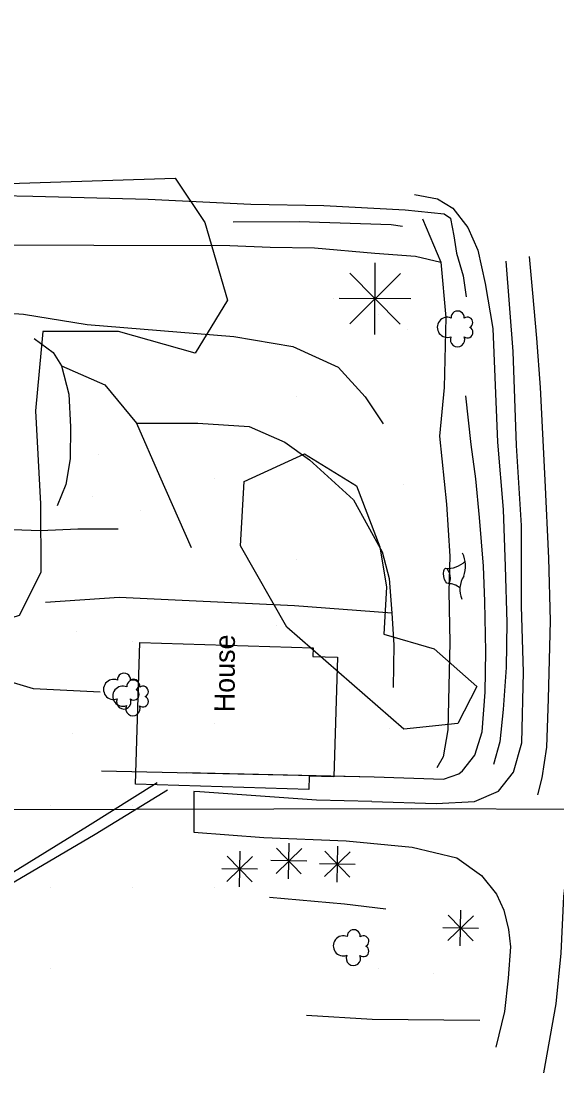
# Model space of a CAD drawing. Extents: x 19528164 to 19545171, y 7585743 to 7602745.
# Drawn here: x 19529637.7 to 19529768.7, y 7587529.5 to 7587786.8 of the extents above; entities that cross this region are included whole.
import ezdxf

# ---------------------------------------------------------------- set-up
doc = ezdxf.new("R2010")
doc.units = 0
for name, color, linetype in [('Default', 7, 'Continuous'), ('PhoBreakLine', 7, 'Continuous'), ('PhoBuilding', 7, 'Continuous'), ('PhoEdgeSidewalk', 7, 'Continuous'), ('PhoISAEPoints', 7, 'Continuous'), ('PhoNotesDesign', 7, 'Continuous'), ('PhoSurveyLimits', 7, 'Continuous'), ('PhoVegetation', 7, 'Continuous'), ('SurBreakLine', 7, 'Continuous'), ('SurEdgeEntranceUnpaved', 7, 'Continuous'), ('SurROWRail', 7, 'Continuous')]:
    doc.layers.add(name, color=color, linetype=linetype)

# ---------------------------------------------------------------- blocks, each defined once
blk = doc.blocks.new('TREV')
at = {"layer": 'Default'}
for p, q in [((0, -8.75), (0, 8.75)), ((-6.18, -6.19), (6.19, 6.18)), ((6.18, -6.18), (-6.18, 6.18)), ((-8.75, 0), (8.75, 0)), ((0, 0), (0, 0))]:
    blk.add_line(p, q, dxfattribs=at)
blk = doc.blocks.new('TRDC')
at = {"layer": 'PhoVegetation'}
for centre, radius, start, end in [((0.07, 3.96), 4.92, 338.2051, 201.7949), ((-5.96, -1.07), 3.52, 65.4824, 294.5175), ((4.86, -1.07), 3.21, 265.9982, 94.0018), ((-2.37, -5.89), 2.68, 142.7501, 335.3223), ((2.46, -5.82), 2.67, 206.5242, 35.4033)]:
    blk.add_arc(centre, radius, start, end, dxfattribs=at)

msp = doc.modelspace()

# ---------------------------------------------------------------- linework, layer by layer
at = {"layer": 'PhoBreakLine'}
for points in [[(19529420.19, 7587746.61), (19529433.66, 7587746.58), (19529450.79, 7587746.1), (19529465.72, 7587745.84), (19529493.29, 7587745.02), (19529503.44, 7587744.9), (19529528.05, 7587744.66), (19529553.91, 7587744.62), (19529574.34, 7587744.69), (19529588.8, 7587744.24), (19529624.68, 7587744.31), (19529640.57, 7587743.93), (19529668.81, 7587743.19), (19529693.9, 7587741.96), (19529711.72, 7587741.66)], [(19529733.91, 7587744.35), (19529739.52, 7587743.26), (19529743.28, 7587741.05), (19529746.97, 7587736.28), (19529749.38, 7587730.72), (19529751.16, 7587722.61), (19529753.05, 7587711.57), (19529754.21, 7587683.76), (19529755.58, 7587667.29), (19529756.09, 7587653.39), (19529756.43, 7587639.73), (19529756.31, 7587628.69), (19529755.56, 7587618.43), (19529754.77, 7587610.51), (19529753.2, 7587604.95)], [(19529156.27, 7587739.82), (19529168.3, 7587739.53), (19529192.58, 7587740.59), (19529208.56, 7587740.78), (19529236.73, 7587740.12), (19529269.19, 7587739.6), (19529293.66, 7587738.67), (19529340.18, 7587738.62), (19529352.73, 7587738.2), (19529419.89, 7587736.21), (19529440.4, 7587735.64), (19529452.89, 7587735.05), (19529493.33, 7587731.91), (19529550.24, 7587733.18), (19529571.65, 7587732.68), (19529583.99, 7587732.56), (19529601.39, 7587732.73), (19529622.17, 7587732.03), (19529688.78, 7587731.89)], [(19529711.72, 7587741.66), (19529731.6, 7587740.61), (19529741.13, 7587739.6), (19529742.67, 7587738.55), (19529742.67, 7587738.53), (19529743.49, 7587734.23), (19529744.17, 7587730.03), (19529745.8, 7587724.47), (19529746.52, 7587719.34)], [(19529689.61, 7587737.66), (19529705.72, 7587737.72), (19529728.21, 7587736.99), (19529730.99, 7587736.58)], [(19529735.82, 7587738.38), (19529740.34, 7587727.82), (19529741.58, 7587714.3), (19529741.12, 7587697.15), (19529739.97, 7587685.24), (19529741.73, 7587668.61), (19529742.5, 7587655.88), (19529742.29, 7587647.28), (19529742.53, 7587634.79)], [(19529688.78, 7587731.89), (19529698.6, 7587731.44), (19529709.44, 7587731.29), (19529724.21, 7587730.01), (19529734.15, 7587729.31), (19529740.34, 7587727.82)], [(19529761.95, 7587729.17), (19529762.73, 7587720.21), (19529763.72, 7587709.19), (19529764.64, 7587697.14), (19529765.75, 7587674.53), (19529766.68, 7587655.45), (19529767.03, 7587640.08), (19529766.6, 7587621), (19529766.17, 7587609.21), (19529765.05, 7587601.68), (19529763.95, 7587597.53)], [(19529616.13, 7587716.64), (19529638.34, 7587715.08), (19529653.91, 7587712.56), (19529689.77, 7587709.6), (19529704.19, 7587707.22), (19529715.24, 7587702.13), (19529721.86, 7587694.89), (19529726.26, 7587688.26)], [(19529640.96, 7587709.15), (19529645.59, 7587705.73), (19529647.58, 7587702.43), (19529649.39, 7587695.49), (19529649.79, 7587687.53), (19529649.7, 7587679.74), (19529648.66, 7587673.47), (19529646.51, 7587668.24)], [(19529647.58, 7587702.43), (19529658.21, 7587697.82), (19529665.92, 7587688.41), (19529671.59, 7587675.53), (19529679.3, 7587658.01)], [(19529745.65, 7587603.4), (19529748.67, 7587607.23), (19529750.4, 7587612.93), (19529751.16, 7587622.62), (19529751.33, 7587632.62), (19529751.1, 7587644.82), (19529750.8, 7587653.47), (19529749.8, 7587665.36), (19529748.89, 7587674.83), (19529747.74, 7587683.22), (19529746.45, 7587695.09)], [(19529665.92, 7587688.41), (19529680.92, 7587688.41), (19529693.48, 7587687.6), (19529702.2, 7587683.78), (19529708.24, 7587679.48), (19529719.02, 7587669.68), (19529725.96, 7587656.95), (19529727.71, 7587650.48), (19529728.34, 7587642.01), (19529728.83, 7587634.27), (19529728.7, 7587623.76)], [(19529661.43, 7587662.5), (19529651.64, 7587662.52), (19529642.47, 7587662.11), (19529610.25, 7587663.29), (19529594.75, 7587663.47), (19529579.01, 7587663.89), (19529567.69, 7587663.74), (19529557.42, 7587664.03), (19529544.08, 7587664.65), (19529532.79, 7587665.08), (19529514.51, 7587665.52), (19529501.64, 7587666.02), (19529483.38, 7587666.28), (19529457.48, 7587666.84), (19529442.28, 7587666.62), (19529431.44, 7587666.63), (19529419.74, 7587667.28)], [(19529728.34, 7587642.01), (19529704.56, 7587643.73), (19529661.7, 7587645.77), (19529643.71, 7587644.56)], [(19529742.53, 7587634.79), (19529742.01, 7587613.45), (19529740.88, 7587606.87), (19529739.36, 7587604.16)], [(19529657.07, 7587622.63), (19529640.76, 7587623.46), (19529622.79, 7587628.88), (19529608.14, 7587630), (19529598.42, 7587630.22), (19529594.53, 7587623.93), (19529581.77, 7587623.64), (19529561.39, 7587624.06), (19529541.38, 7587623.79), (19529529.93, 7587623.48), (19529509.74, 7587623.42), (19529489.3, 7587626.92), (19529467.48, 7587626.59), (19529451.67, 7587626.55), (19529434.68, 7587626.08), (19529420.65, 7587625.99), (19529408.42, 7587625.79)], [(19529678.08, 7587602.97), (19529724.04, 7587601.96), (19529740.99, 7587601.4), (19529744.74, 7587602.72), (19529745.65, 7587603.4)], [(19529773.73, 7587595.86), (19529771.92, 7587586.54), (19529770.3, 7587572.67), (19529769.64, 7587558.83), (19529768.43, 7587546.45), (19529765.4, 7587529.53)], [(19529698.42, 7587572.51), (19529716.8, 7587570.93), (19529726.89, 7587569.7)], [(19529707.5, 7587543.64), (19529723.57, 7587542.67), (19529749.85, 7587542.46)]]:
    msp.add_lwpolyline(points, dxfattribs=at)
at = {"layer": 'PhoBuilding'}
msp.add_lwpolyline([(19529666.77, 7587634.77), (19529709.1, 7587633.47), (19529709.04, 7587631.41), (19529715.11, 7587631.23), (19529714.21, 7587601.93), (19529708.19, 7587602.11), (19529708.09, 7587598.85), (19529665.71, 7587600.15)], close=True, dxfattribs=at)
msp.add_lwpolyline([(19529666.77, 7587634.77), (19529709.1, 7587633.47), (19529709.04, 7587631.41), (19529715.11, 7587631.23), (19529714.21, 7587601.93), (19529708.19, 7587602.11), (19529708.09, 7587598.85), (19529665.71, 7587600.15)], close=True, dxfattribs=at)
msp.add_lwpolyline([(19529666.77, 7587634.77), (19529709.1, 7587633.47), (19529709.04, 7587631.41), (19529715.11, 7587631.23), (19529714.21, 7587601.93), (19529708.19, 7587602.11), (19529708.09, 7587598.85), (19529665.71, 7587600.15)], close=True, dxfattribs=at)
at = {"layer": 'PhoEdgeSidewalk'}
for points in [[(19529671, 7587600.46), (19529653.97, 7587589.79), (19529635.89, 7587578.66), (19529631.36, 7587576.54), (19529599.21, 7587576.57)], [(19529600.5, 7587573.15), (19529622.4, 7587573.43), (19529631.81, 7587573.83), (19529655.83, 7587587.91), (19529673.53, 7587598.74)]]:
    msp.add_lwpolyline(points, dxfattribs=at)
at = {"layer": 'PhoISAEPoints'}
for p, q in [((19529714.16, 7587718.82), (19529714.16, 7587718.82)), ((19529725, 7587715), (19529725, 7587715)), ((19529732.07, 7587711.27), (19529732.07, 7587711.27)), ((19529705, 7587695), (19529705, 7587695)), ((19529705, 7587695), (19529705, 7587695)), ((19529705, 7587695), (19529705, 7587695)), ((19529656.61, 7587680.81), (19529656.61, 7587680.81)), ((19529685, 7587675), (19529685, 7587675)), ((19529685, 7587675), (19529685, 7587675)), ((19529685, 7587675), (19529685, 7587675)), ((19529731.2, 7587673.36), (19529731.2, 7587673.36)), ((19529655.11, 7587670.62), (19529655.11, 7587670.62)), ((19529667.03, 7587667.01), (19529667.03, 7587667.01)), ((19529705, 7587655), (19529705, 7587655)), ((19529651.19, 7587637.51), (19529651.19, 7587637.51)), ((19529700.05, 7587638.94), (19529700.05, 7587638.94)), ((19529665, 7587635), (19529665, 7587635)), ((19529685, 7587615), (19529685, 7587615)), ((19529727.7, 7587613.86), (19529727.7, 7587613.86)), ((19529725, 7587555), (19529725, 7587555)), ((19529738.49, 7587553.87), (19529738.49, 7587553.87))]:
    msp.add_line(p, q, dxfattribs=at)
at = {"layer": 'PhoSurveyLimits'}
msp.add_lwpolyline([(19532927.8, 7588415.02), (19531060.74, 7587591.82), (19530315.47, 7587591.82), (19529733.27, 7587594.16), (19528768.59, 7587591.82), (19528359.06, 7587591.82), (19528383.91, 7589187.36), (19529003.19, 7589193.14), (19529457, 7588986.74), (19529383.8, 7588810.24), (19529181.3, 7588824.95), (19528822.49, 7588987.64), (19528768.59, 7587951.55), (19530119.99, 7587951.55), (19530497.83, 7588049.69), (19530813.08, 7588141.83), (19530826.36, 7590306.58)], dxfattribs=at)
at = {"layer": 'PhoVegetation'}
for p, q in [((19529703.12, 7587577.01), (19529703.26, 7587585.76)), ((19529691.11, 7587575.03), (19529691.26, 7587583.78)), ((19529691.11, 7587575.03), (19529691.26, 7587583.78)), ((19529691.11, 7587575.03), (19529691.26, 7587583.78)), ((19529706.33, 7587584.42), (19529700.05, 7587578.34)), ((19529706.23, 7587578.24), (19529700.15, 7587584.53)), ((19529718.19, 7587583.63), (19529711.91, 7587577.55)), ((19529718.09, 7587577.45), (19529712.01, 7587583.74)), ((19529714.98, 7587576.22), (19529715.12, 7587584.97)), ((19529694.33, 7587582.45), (19529688.04, 7587576.37)), ((19529694.33, 7587582.45), (19529688.04, 7587576.37)), ((19529694.33, 7587582.45), (19529688.04, 7587576.37)), ((19529694.23, 7587576.26), (19529688.14, 7587582.55)), ((19529694.23, 7587576.26), (19529688.14, 7587582.55)), ((19529694.23, 7587576.26), (19529688.14, 7587582.55)), ((19529707.56, 7587581.31), (19529698.82, 7587581.46)), ((19529703.19, 7587581.38), (19529703.19, 7587581.38)), ((19529719.42, 7587580.52), (19529710.68, 7587580.66)), ((19529715.05, 7587580.59), (19529715.05, 7587580.59)), ((19529695.56, 7587579.33), (19529686.81, 7587579.48)), ((19529695.56, 7587579.33), (19529686.81, 7587579.48)), ((19529695.56, 7587579.33), (19529686.81, 7587579.48)), ((19529691.18, 7587579.41), (19529691.18, 7587579.41)), ((19529691.18, 7587579.41), (19529691.18, 7587579.41)), ((19529691.18, 7587579.41), (19529691.18, 7587579.41)), ((19529748.31, 7587567.99), (19529742.02, 7587561.91)), ((19529748.21, 7587561.81), (19529742.13, 7587568.1)), ((19529745.09, 7587560.58), (19529745.24, 7587569.33)), ((19529749.54, 7587564.88), (19529740.79, 7587565.02)), ((19529745.17, 7587564.95), (19529745.17, 7587564.95))]:
    msp.add_line(p, q, dxfattribs=at)
for points in [[(19529608.94, 7587643.61), (19529606.59, 7587660.06), (19529616.14, 7587680.9), (19529619.69, 7587696.6), (19529611.14, 7587719.56), (19529594.43, 7587720.78), (19529577.56, 7587724.78), (19529573.08, 7587738.13), (19529578.8, 7587745.28), (19529675.41, 7587748.37), (19529682.64, 7587737.51), (19529688.21, 7587718.53), (19529680.27, 7587705.53), (19529661.58, 7587710.83), (19529643.02, 7587710.83), (19529641.23, 7587691.45), (19529642.48, 7587668.7), (19529642.55, 7587651.93), (19529637.3, 7587641.43), (19529619.37, 7587635.68)], [(19529702.71, 7587638.52), (19529691.35, 7587658.48), (19529692.29, 7587674.19), (19529706.99, 7587680.9), (19529719.76, 7587673.13), (19529725.41, 7587658.16), (19529727.07, 7587648.34), (19529726.44, 7587636.81), (19529738.74, 7587633.28), (19529749.16, 7587624.02), (19529744.53, 7587614.96), (19529731.32, 7587613.59)]]:
    msp.add_lwpolyline(points, close=True, dxfattribs=at)
for centre, radius, start, end in [((19529739.03, 7587653.49), 7.33, 340.2407, 25.4804), ((19529742.04, 7587658.98), 6.05, 264.524, 314.3156), ((19529751.08, 7587647.75), 6.1, 147.7204, 202.7444), ((19529742.21, 7587644.99), 4.21, 48.5301, 90.8705), ((19529662.6, 7587621.67), 2.46, 67.2515, 290.8414), ((19529665.15, 7587624.03), 1.6, 355.0446, 183.0483), ((19529667.5, 7587622.79), 1.34, 295.5706, 124.4498), ((19529667.5, 7587620.37), 1.34, 231.7966, 64.3688), ((19529665.06, 7587618.62), 1.76, 154.5289, 23.564), ((19529716.5, 7587560.61), 2.46, 67.2515, 290.8414), ((19529719.05, 7587562.97), 1.6, 355.0446, 183.0483), ((19529721.41, 7587561.73), 1.34, 295.5706, 124.4498), ((19529721.4, 7587559.31), 1.34, 231.7966, 64.3688), ((19529718.96, 7587557.56), 1.76, 154.5289, 23.564)]:
    msp.add_arc(centre, radius, start, end, dxfattribs=at)
msp.add_ellipse((19529741.8, 7587651.08), major_axis=(0.34, -1.88), ratio=0.385758, dxfattribs=at)
at = {"layer": 'SurBreakLine'}
msp.add_lwpolyline([(19529657.39, 7587603.43), (19529724.04, 7587601.96), (19529740.99, 7587601.4), (19529744.74, 7587602.72), (19529745.65, 7587603.4)], dxfattribs=at)
at = {"layer": 'SurEdgeEntranceUnpaved'}
for p, q in [((19529650.18, 7587612.47), (19529650.18, 7587612.47)), ((19529645, 7587595), (19529645, 7587595)), ((19529645, 7587595), (19529645, 7587595)), ((19529645, 7587595), (19529645, 7587595)), ((19529665, 7587595), (19529665, 7587595)), ((19529665, 7587595), (19529665, 7587595)), ((19529645, 7587575), (19529645, 7587575)), ((19529665, 7587575), (19529665, 7587575)), ((19529685, 7587575), (19529685, 7587575)), ((19529645, 7587555), (19529645, 7587555))]:
    msp.add_line(p, q, dxfattribs=at)
at = {"layer": 'SurROWRail'}
for points in [[(19529723.51, 7587595.89), (19529739.2, 7587595.4), (19529748.55, 7587595.88), (19529754.43, 7587598.41), (19529758.11, 7587603.09), (19529760.14, 7587610.23), (19529760.54, 7587627.51), (19529760.06, 7587643.7), (19529760.05, 7587663.4), (19529758.84, 7587683.01), (19529758.02, 7587705.98), (19529756.29, 7587728.03)], [(19529723.51, 7587595.89), (19529709.94, 7587596.21), (19529681.4, 7587598.3), (19529679.93, 7587598.35), (19529679.97, 7587588.41), (19529697.1, 7587587.12), (19529717.16, 7587586.32), (19529733.36, 7587584.72), (19529744.23, 7587582.17), (19529750.27, 7587577.79), (19529753.94, 7587573.22), (19529755.76, 7587569.34), (19529756.89, 7587564.6), (19529757.4, 7587560.4), (19529756.83, 7587552.7), (19529755.9, 7587544.59), (19529753.81, 7587535.85)], [(19529723.51, 7587595.89), (19529709.94, 7587596.21), (19529681.4, 7587598.3), (19529679.93, 7587598.35), (19529679.97, 7587588.41), (19529697.1, 7587587.12), (19529717.16, 7587586.32), (19529733.36, 7587584.72), (19529744.23, 7587582.17), (19529750.27, 7587577.79), (19529753.94, 7587573.22), (19529755.76, 7587569.34), (19529756.89, 7587564.6), (19529757.4, 7587560.4), (19529756.83, 7587552.7), (19529755.9, 7587544.59), (19529753.81, 7587535.85)]]:
    msp.add_lwpolyline(points, dxfattribs=at)

# ---------------------------------------------------------------- block references
at = {"layer": 'PhoVegetation', "rotation": 89.64760321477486}
for name, p, xscale, yscale in [('TREV', (19529724.27, 7587718.86), 0.9999999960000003, 0.9999999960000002), ('TRDC', (19529743.9, 7587711.83), 0.49999999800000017, 0.4999999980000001), ('TRDC', (19529662.32, 7587623.27), 0.49999999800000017, 0.4999999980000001)]:
    msp.add_blockref(name, p, dxfattribs=dict(at, xscale=xscale, yscale=yscale))

# ---------------------------------------------------------------- texts
at = {"layer": 'PhoNotesDesign'}
msp.add_text('House', height=4.92, rotation=89.6898, dxfattribs=at).set_placement((19529689.91, 7587617.73))

doc.saveas('drawing.dxf')
